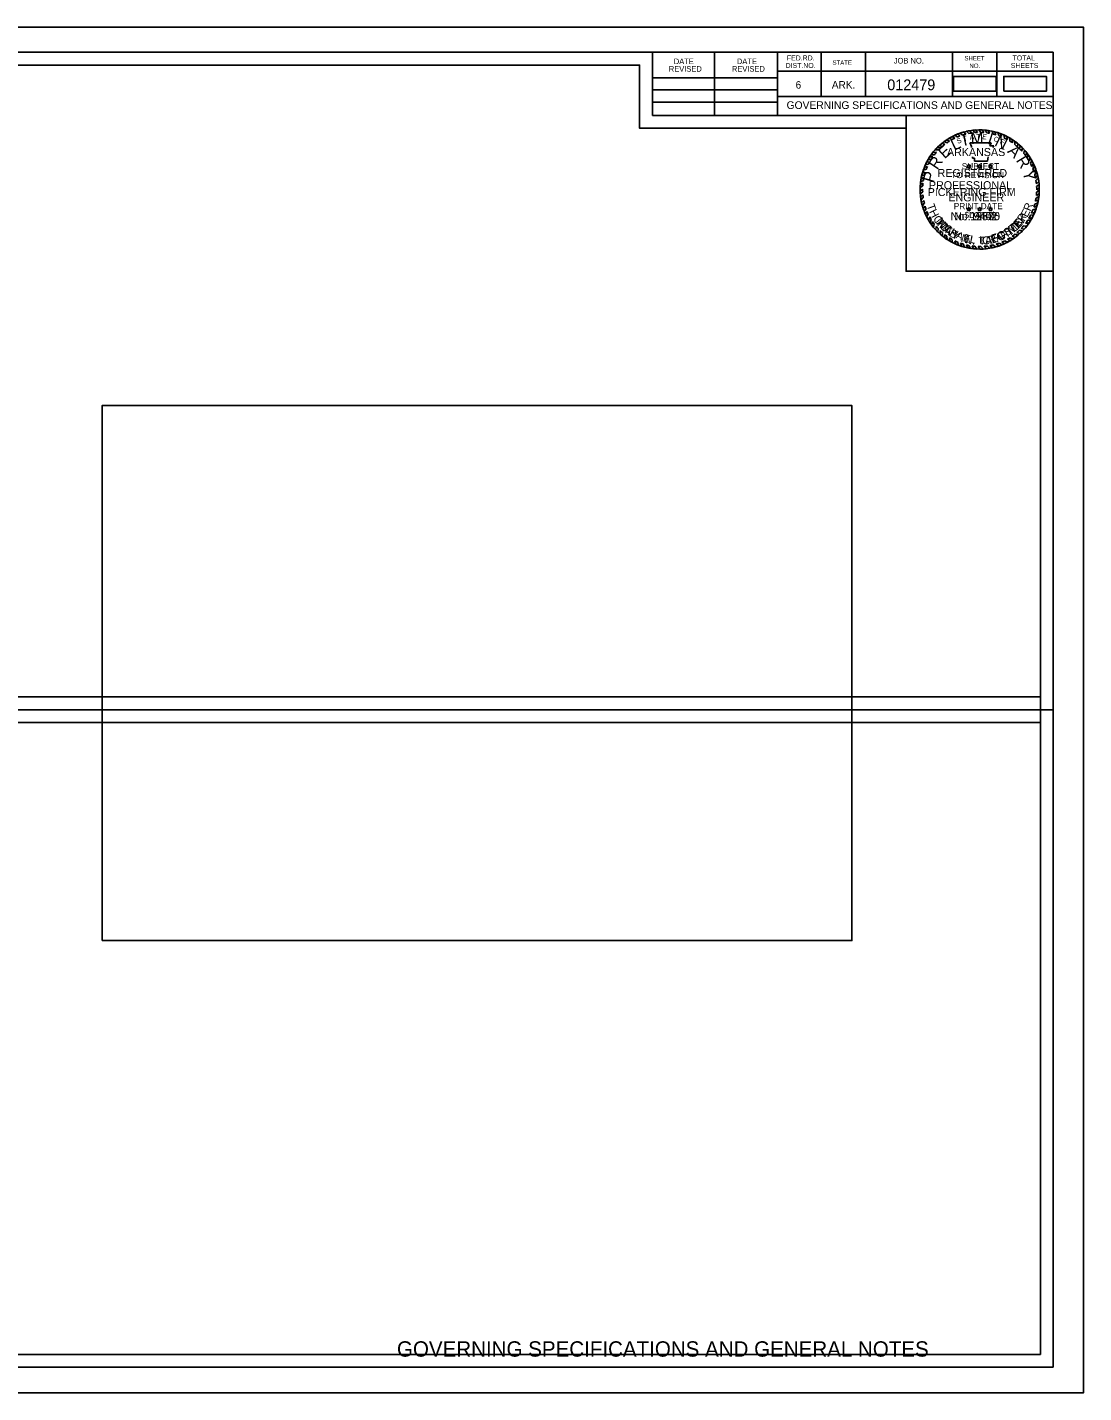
# Model space of a CAD drawing. Extents: x 1369290 to 1369980, y 379348 to 379562.
# Drawn here: x 1369815.1 to 1369980.2, y 379348.4 to 379561.7 of the extents above; entities that cross this region are included whole.
import ezdxf

# ---------------------------------------------------------------- set-up
doc = ezdxf.new("R2010")
doc.units = 0
for name, color, linetype in [('Default', 7, 'Continuous'), ('R_Border', 7, 'Continuous'), ('R_Border Notes', 7, 'Continuous'), ('R_Border Plan-Plan', 7, 'Continuous'), ('R_Border Title', 7, 'Continuous'), ('R_No Plot', 7, 'Continuous'), ('STAMP_PE_CRAFTON', 7, 'Continuous'), ('STAMP_PE_FOSTER', 7, 'Continuous'), ('STAMP_PE_SEAL-INFO', 7, 'Continuous'), ('STAMP_PE_TAEGTMEYER', 7, 'Continuous'), ('STAMP_PE_TXT', 7, 'Continuous'), ('STAMP_PRELIMINARY', 7, 'Continuous')]:
    doc.layers.add(name, color=color, linetype=linetype)

msp = doc.modelspace()

# ---------------------------------------------------------------- linework, layer by layer
at = {"layer": 'Default'}
for points in [[(1369959.8, 379551.74), (1369966.48, 379551.74), (1369966.48, 379554.05), (1369959.8, 379554.05)], [(1369967.67, 379551.74), (1369974.35, 379551.74), (1369974.35, 379554.05), (1369967.67, 379554.05)], [(1369826.78, 379419.02), (1369943.94, 379419.02), (1369943.94, 379502.63), (1369826.78, 379502.63)]]:
    msp.add_lwpolyline(points, close=True, dxfattribs=at)
at = {"layer": 'R_Border'}
for p, q in [((1369659.23, 379557.83), (1369975.41, 379557.83)), ((1369912.77, 379547.95), (1369912.77, 379557.83)), ((1369922.45, 379547.95), (1369922.45, 379557.83)), ((1369932.31, 379557.83), (1369932.31, 379547.95)), ((1369939.15, 379557.83), (1369939.15, 379550.89)), ((1369946.09, 379557.83), (1369946.09, 379550.89)), ((1369959.67, 379557.83), (1369959.67, 379550.89)), ((1369966.61, 379557.83), (1369966.61, 379550.89)), ((1369975.41, 379352.37), (1369975.41, 379557.83)), ((1369912.77, 379553.81), (1369932.31, 379553.81)), ((1369975.41, 379554.89), (1369932.31, 379554.89)), ((1369975.41, 379554.91), (1369975.41, 379554.91)), ((1369912.77, 379551.95), (1369932.31, 379551.95)), ((1369912.77, 379550.01), (1369932.31, 379550.01)), ((1369975.41, 379550.89), (1369932.31, 379550.89)), ((1369935.27, 379550.89), (1369975.41, 379550.89)), ((1369975.41, 379547.95), (1369912.77, 379547.95)), ((1369975.41, 379352.37), (1369659.23, 379352.37))]:
    msp.add_line(p, q, dxfattribs=at)
at = {"layer": 'R_Border Plan-Plan'}
msp.add_line((1369659.23, 379455.1), (1369975.41, 379455.1), dxfattribs=at)
at = {"layer": 'R_No Plot'}
for points in [[(1369646.82, 379561.73), (1369980.16, 379561.73), (1369980.16, 379348.39), (1369646.82, 379348.39)], [(1369973.41, 379457.1), (1369661.23, 379457.1), (1369661.23, 379555.83), (1369910.77, 379555.83), (1369910.77, 379545.95), (1369928.31, 379545.95), (1369952.41, 379545.95), (1369952.41, 379523.62), (1369973.41, 379523.62)], [(1369661.23, 379555.83), (1369910.77, 379555.83), (1369910.77, 379545.95), (1369928.31, 379545.95), (1369952.41, 379545.95), (1369952.41, 379523.62), (1369973.41, 379523.62), (1369973.41, 379354.37), (1369661.23, 379354.37)], [(1369952.41, 379547.95), (1369975.41, 379547.95), (1369975.41, 379523.62), (1369952.41, 379523.62)], [(1369661.23, 379453.1), (1369973.41, 379453.1), (1369973.41, 379354.37), (1369661.23, 379354.37)]]:
    msp.add_lwpolyline(points, close=True, dxfattribs=at)
at = {"layer": 'STAMP_PE_SEAL-INFO'}
for p, q in [((1369960.02, 379544.86), (1369960.41, 379544.59)), ((1369960.52, 379545.08), (1369960.82, 379544.75)), ((1369960.87, 379545.21), (1369961.25, 379544.9)), ((1369961.46, 379545.39), (1369961.75, 379545.04)), ((1369961.85, 379545.49), (1369962.21, 379545.14)), ((1369962.33, 379545.58), (1369962.63, 379545.22)), ((1369962.85, 379545.66), (1369963.13, 379545.27)), ((1369963.58, 379545.3), (1369963.27, 379545.7)), ((1369964.08, 379545.31), (1369963.8, 379545.72)), ((1369964.54, 379545.29), (1369964.28, 379545.71)), ((1369965.05, 379545.24), (1369964.75, 379545.68)), ((1369965.47, 379545.17), (1369965.21, 379545.63)), ((1369966.03, 379545.05), (1369965.86, 379545.51)), ((1369966.44, 379544.94), (1369966.28, 379545.41)), ((1369966.89, 379544.8), (1369966.75, 379545.28)), ((1369967.31, 379544.64), (1369967.16, 379545.13)), ((1369967.77, 379544.43), (1369967.66, 379544.93)), ((1369968.21, 379544.2), (1369968.13, 379544.71)), ((1369956.95, 379542.6), (1369957.47, 379542.56)), ((1369957.27, 379542.94), (1369957.82, 379542.9)), ((1369957.61, 379543.26), (1369958.07, 379543.12)), ((1369957.95, 379543.56), (1369958.48, 379543.46)), ((1369958.33, 379543.89), (1369958.79, 379543.69)), ((1369958.75, 379544.16), (1369959.19, 379543.96)), ((1369959.14, 379544.4), (1369959.57, 379544.18)), ((1369959.59, 379544.65), (1369960.05, 379544.43)), ((1369962.39, 379543.69), (1369965.73, 379543.69)), ((1369962.51, 379543.38), (1369962.39, 379543.69)), ((1369962.61, 379543.08), (1369962.51, 379543.38)), ((1369962.62, 379542.97), (1369962.61, 379543.08)), ((1369965.73, 379543.69), (1369965.5, 379543.19)), ((1369965.5, 379543.19), (1369966.14, 379543.19)), ((1369966.14, 379543.19), (1369965.99, 379542.97)), ((1369968.6, 379543.98), (1369968.56, 379544.48)), ((1369969.03, 379543.69), (1369969, 379544.2)), ((1369969.4, 379543.42), (1369969.43, 379543.91)), ((1369969.84, 379543.05), (1369969.86, 379543.57)), ((1369970.15, 379542.76), (1369970.22, 379543.26)), ((1369970.51, 379542.38), (1369970.58, 379542.91)), ((1369970.79, 379542.07), (1369970.92, 379542.54)), ((1369955.62, 379540.65), (1369956.11, 379540.71)), ((1369955.85, 379541.07), (1369956.34, 379541.09)), ((1369956.09, 379541.47), (1369956.61, 379541.5)), ((1369956.33, 379541.82), (1369956.83, 379541.81)), ((1369956.61, 379542.18), (1369957.15, 379542.21)), ((1369962.81, 379541.26), (1369962.78, 379541.48)), ((1369963.12, 379541.26), (1369962.81, 379541.26)), ((1369963.12, 379540.83), (1369963.12, 379541.26)), ((1369965.15, 379540.83), (1369963.12, 379540.83)), ((1369965.17, 379541.17), (1369965.15, 379540.83)), ((1369965.25, 379541.48), (1369965.17, 379541.17)), ((1369971.11, 379541.65), (1369971.25, 379542.15)), ((1369971.33, 379541.34), (1369971.51, 379541.8)), ((1369971.64, 379540.84), (1369971.82, 379541.33)), ((1369971.84, 379540.47), (1369972.07, 379540.92)), ((1369972.07, 379539.99), (1369972.3, 379540.47)), ((1369955.2, 379538.26), (1369954.73, 379538.01)), ((1369954.83, 379538.51), (1369955.3, 379538.7)), ((1369954.94, 379538.92), (1369955.41, 379539.08)), ((1369955.09, 379539.42), (1369955.58, 379539.56)), ((1369955.24, 379539.83), (1369955.75, 379539.97)), ((1369955.43, 379540.26), (1369955.93, 379540.36)), ((1369972.21, 379539.65), (1369972.47, 379540.08)), ((1369972.4, 379539.1), (1369972.68, 379539.58)), ((1369972.51, 379538.74), (1369972.81, 379539.19)), ((1369972.65, 379538.18), (1369972.96, 379538.63)), ((1369955.02, 379536.94), (1369954.59, 379536.69)), ((1369955, 379536.45), (1369954.59, 379536.11)), ((1369955.05, 379537.37), (1369954.62, 379537.09)), ((1369955.11, 379537.8), (1369954.67, 379537.58)), ((1369972.71, 379537.8), (1369973.07, 379538.15)), ((1369972.78, 379537.29), (1369973.15, 379537.63)), ((1369972.81, 379536.87), (1369973.2, 379537.16)), ((1369972.81, 379535.95), (1369973.23, 379536.22)), ((1369972.83, 379536.35), (1369973.23, 379536.67)), ((1369955.01, 379536.04), (1369954.61, 379535.72)), ((1369955.04, 379535.55), (1369954.67, 379535.19)), ((1369955.09, 379535.12), (1369954.74, 379534.74)), ((1369955.17, 379534.66), (1369954.83, 379534.29)), ((1369955.26, 379534.24), (1369954.95, 379533.83)), ((1369972.53, 379534.1), (1369973, 379534.3)), ((1369972.63, 379534.55), (1369973.09, 379534.75)), ((1369972.72, 379535.05), (1369973.17, 379535.27)), ((1369972.77, 379535.44), (1369973.21, 379535.7)), ((1369955.39, 379533.79), (1369955.09, 379533.38)), ((1369955.53, 379533.37), (1369955.25, 379532.96)), ((1369955.69, 379532.94), (1369955.43, 379532.52)), ((1369955.87, 379532.56), (1369955.64, 379532.1)), ((1369956.1, 379532.1), (1369955.91, 379531.61)), ((1369971.6, 379531.88), (1369972.1, 379531.93)), ((1369971.87, 379532.38), (1369972.36, 379532.44)), ((1369972.03, 379532.71), (1369972.52, 379532.81)), ((1369972.24, 379533.23), (1369972.73, 379533.36)), ((1369972.38, 379533.61), (1369972.87, 379533.81)), ((1369956.34, 379531.7), (1369956.15, 379531.23)), ((1369956.54, 379531.39), (1369956.43, 379530.83)), ((1369956.82, 379531), (1369956.72, 379530.47)), ((1369957.12, 379530.62), (1369957.04, 379530.1)), ((1369957.43, 379530.28), (1369957.36, 379529.76)), ((1369957.75, 379529.96), (1369957.72, 379529.43)), ((1369970.14, 379530.02), (1369970.58, 379529.88)), ((1369970.39, 379530.28), (1369970.87, 379530.19)), ((1369970.78, 379530.71), (1369971.24, 379530.63)), ((1369971.09, 379531.1), (1369971.59, 379531.11)), ((1369971.43, 379531.6), (1369971.9, 379531.59)), ((1369958.09, 379529.64), (1369958.09, 379529.11)), ((1369958.45, 379529.35), (1369958.47, 379528.82)), ((1369958.79, 379529.1), (1369958.83, 379528.58)), ((1369959.22, 379528.82), (1369959.28, 379528.3)), ((1369959.57, 379528.61), (1369959.66, 379528.1)), ((1369960.05, 379528.36), (1369960.21, 379527.84)), ((1369960.42, 379528.19), (1369960.6, 379527.68)), ((1369960.91, 379528), (1369961.12, 379527.5)), ((1369961.32, 379527.87), (1369961.55, 379527.38)), ((1369961.83, 379527.73), (1369962.04, 379527.26)), ((1369962.23, 379527.64), (1369962.48, 379527.18)), ((1369965.51, 379527.63), (1369965.9, 379527.29)), ((1369966.01, 379527.73), (1369966.38, 379527.41)), ((1369966.47, 379527.85), (1369966.88, 379527.56)), ((1369966.96, 379528.02), (1369967.4, 379527.75)), ((1369967.38, 379528.18), (1369967.8, 379527.92)), ((1369967.84, 379528.39), (1369968.32, 379528.18)), ((1369968.24, 379528.6), (1369968.66, 379528.37)), ((1369968.66, 379528.85), (1369969.11, 379528.65)), ((1369969, 379529.08), (1369969.44, 379528.89)), ((1369969.46, 379529.42), (1369969.93, 379529.27)), ((1369969.73, 379529.64), (1369970.21, 379529.52)), ((1369962.73, 379527.56), (1369962.97, 379527.12)), ((1369963.17, 379527.51), (1369963.44, 379527.08)), ((1369963.65, 379527.48), (1369963.95, 379527.07)), ((1369964.11, 379527.48), (1369964.45, 379527.09)), ((1369964.63, 379527.51), (1369964.96, 379527.13)), ((1369965.07, 379527.56), (1369965.44, 379527.2))]:
    msp.add_line(p, q, dxfattribs=at)
for radius, start, end in [(9.32, 111.3124, 114.7026), (8.91, 110.3086, 113.1659), (9.32, 105.2339, 109.0352), (8.91, 104.0352, 107.3615), (9.32, 99.7525, 102.7765), (8.91, 98.258, 101.0329), (9.32, 93.9381, 96.5517), (8.91, 92.1102, 95.0367), (9.32, 87.7298, 90.6707), (8.91, 85.9628, 88.9097), (9.32, 81.9732, 84.8236), (8.91, 79.9264, 82.696), (9.32, 75.3125, 77.9426), (8.91, 73.5575, 76.2314), (9.32, 69.6061, 72.3058), (8.91, 67.6248, 70.504), (9.32, 63.1329, 66.2704), (9.32, 135.4021, 138.3031), (8.91, 133.1331, 136.2562), (9.32, 129.7326, 132.5376), (8.91, 127.5297, 130.9683), (9.32, 123.6199, 126.5906), (8.91, 121.9746, 125.11), (9.32, 117.6544, 120.8099), (8.91, 115.6869, 119.1583), (8.91, 61.1558, 64.3784), (9.32, 56.9003, 60.0942), (8.91, 54.9238, 58.2702), (8.91, 48.3016, 52.0395), (9.32, 50.3492, 53.7159), (8.91, 42.2212, 45.5512), (9.32, 44.3405, 47.3929), (9.32, 38.1247, 41.2316), (9.32, 152.864, 155.5189), (9.32, 147.0072, 149.899), (8.91, 151.0315, 153.573), (9.32, 141.6056, 144.4486), (8.91, 145.0197, 148.2104), (8.91, 139.301, 142.5873), (8.91, 36.135, 39.5311), (8.91, 29.9032, 33.6645), (9.32, 31.9614, 35.4294), (8.91, 23.7732, 27.2211), (9.32, 25.9391, 29.0125), (9.32, 164.3068, 166.894), (9.32, 158.4077, 161.0701), (8.91, 167.9048, 170.9039), (8.91, 162.4331, 165.0013), (8.91, 156.3402, 159.2319), (8.91, 17.6802, 21.4251), (9.32, 19.9538, 23.3141), (8.91, 11.5444, 15.2364), (9.32, 13.8421, 17.4447), (9.32, 175.7409, 178.2066), (9.32, 170.0003, 172.6878), (8.91, 179.6454, 182.2633), (8.91, 173.73, 176.4734), (8.91, 5.7599, 9.0606), (8.91, 359.7329, 3.0639), (9.32, 7.5852, 10.8621), (9.32, 1.7215, 4.7268), (9.32, 355.7156, 358.9569), (9.32, 181.7251, 184.1626), (9.32, 187.4204, 190.1927), (9.32, 193.0369, 195.9973), (8.91, 185.4539, 188.234), (8.91, 191.2274, 193.9858), (8.91, 341.777, 345.0925), (8.91, 348.0778, 351.3435), (8.91, 353.8632, 357.1274), (9.32, 343.8925, 347.035), (9.32, 349.8305, 353.0885), (9.32, 198.8967, 201.6281), (8.91, 196.9675, 199.8353), (9.32, 204.5479, 207.4328), (8.91, 202.7761, 205.4791), (8.91, 208.7883, 211.7934), (8.91, 329.5549, 333.2076), (8.91, 335.6038, 339.1858), (9.32, 331.4037, 334.9332), (9.32, 337.3837, 340.9933), (9.32, 210.8636, 213.6571), (9.32, 216.6115, 219.491), (8.91, 214.1838, 217.2747), (9.32, 222.48, 225.3801), (8.91, 220.3909, 223.3056), (8.91, 226.2494, 229.2407), (8.91, 310.7744, 314.3161), (9.32, 312.4518, 315.6633), (8.91, 316.6531, 320.3711), (9.32, 318.2846, 321.8043), (8.91, 323.5851, 327.4407), (9.32, 325.4405, 328.9872), (9.32, 228.3665, 231.348), (8.91, 232.229, 234.9336), (9.32, 234.295, 236.9452), (8.91, 238.2223, 240.8353), (9.32, 240.1977, 242.8613), (8.91, 244.3204, 246.9486), (9.32, 246.576, 249.1558), (8.91, 250.3491, 253.1216), (8.91, 256.505, 259.1192), (8.91, 280.3459, 283.5814), (8.91, 286.6423, 289.9783), (9.32, 288.5709, 291.9733), (8.91, 292.8745, 296.1185), (9.32, 294.6481, 298.2166), (8.91, 299.0768, 302.1724), (9.32, 300.621, 303.8703), (8.91, 304.823, 308.5143), (9.32, 306.3721, 310.208), (9.32, 252.5967, 255.3252), (9.32, 258.4433, 261.1398), (8.91, 262.3783, 265.2012), (9.32, 264.1978, 267.1009), (8.91, 268.3215, 271.277), (9.32, 270.2548, 273.3361), (8.91, 274.6157, 277.4486), (9.32, 276.4239, 279.4357), (9.32, 282.3199, 285.3702)]:
    msp.add_arc((1369963.91, 379536.39), radius, start, end, dxfattribs=at)
at = {"layer": 'STAMP_PE_TXT'}
for p, q in [((1369962.09, 379539.97), (1369961.89, 379540.11)), ((1369961.89, 379540.11), (1369962.14, 379540.11)), ((1369962.02, 379539.73), (1369962.09, 379539.97)), ((1369962.21, 379539.88), (1369962.02, 379539.73)), ((1369962.14, 379540.11), (1369962.21, 379540.34)), ((1369962.21, 379540.34), (1369962.29, 379540.11)), ((1369962.41, 379539.73), (1369962.21, 379539.88)), ((1369962.29, 379540.11), (1369962.54, 379540.11)), ((1369962.54, 379540.11), (1369962.34, 379539.97)), ((1369962.34, 379539.97), (1369962.41, 379539.73)), ((1369963.79, 379539.97), (1369963.59, 379540.11)), ((1369963.59, 379540.11), (1369963.84, 379540.11)), ((1369963.71, 379539.73), (1369963.79, 379539.97)), ((1369963.91, 379539.88), (1369963.71, 379539.73)), ((1369963.84, 379540.11), (1369963.91, 379540.34)), ((1369963.91, 379540.34), (1369963.99, 379540.11)), ((1369964.11, 379539.73), (1369963.91, 379539.88)), ((1369963.99, 379540.11), (1369964.23, 379540.11)), ((1369964.23, 379540.11), (1369964.04, 379539.97)), ((1369964.04, 379539.97), (1369964.11, 379539.73)), ((1369965.49, 379539.97), (1369965.29, 379540.11)), ((1369965.29, 379540.11), (1369965.53, 379540.11)), ((1369965.41, 379539.73), (1369965.49, 379539.97)), ((1369965.61, 379539.88), (1369965.41, 379539.73)), ((1369965.53, 379540.11), (1369965.61, 379540.34)), ((1369965.61, 379540.34), (1369965.69, 379540.11)), ((1369965.81, 379539.73), (1369965.61, 379539.88)), ((1369965.69, 379540.11), (1369965.93, 379540.11)), ((1369965.93, 379540.11), (1369965.73, 379539.97)), ((1369965.73, 379539.97), (1369965.81, 379539.73)), ((1369962.09, 379533.26), (1369961.89, 379533.4)), ((1369961.89, 379533.4), (1369962.14, 379533.4)), ((1369962.02, 379533.03), (1369962.09, 379533.26)), ((1369962.21, 379533.17), (1369962.02, 379533.03)), ((1369962.14, 379533.4), (1369962.21, 379533.64)), ((1369962.21, 379533.64), (1369962.29, 379533.4)), ((1369962.41, 379533.03), (1369962.21, 379533.17)), ((1369962.29, 379533.4), (1369962.54, 379533.4)), ((1369962.54, 379533.4), (1369962.34, 379533.26)), ((1369962.34, 379533.26), (1369962.41, 379533.03)), ((1369963.79, 379533.26), (1369963.59, 379533.4)), ((1369963.59, 379533.4), (1369963.84, 379533.4)), ((1369963.71, 379533.03), (1369963.79, 379533.26)), ((1369963.91, 379533.17), (1369963.71, 379533.03)), ((1369963.84, 379533.4), (1369963.91, 379533.64)), ((1369963.91, 379533.64), (1369963.99, 379533.4)), ((1369964.11, 379533.03), (1369963.91, 379533.17)), ((1369963.99, 379533.4), (1369964.23, 379533.4)), ((1369964.23, 379533.4), (1369964.04, 379533.26)), ((1369964.04, 379533.26), (1369964.11, 379533.03)), ((1369965.49, 379533.26), (1369965.29, 379533.4)), ((1369965.29, 379533.4), (1369965.53, 379533.4)), ((1369965.41, 379533.03), (1369965.49, 379533.26)), ((1369965.61, 379533.17), (1369965.41, 379533.03)), ((1369965.53, 379533.4), (1369965.61, 379533.64)), ((1369965.61, 379533.64), (1369965.69, 379533.4)), ((1369965.81, 379533.03), (1369965.61, 379533.17)), ((1369965.69, 379533.4), (1369965.93, 379533.4)), ((1369965.93, 379533.4), (1369965.73, 379533.26)), ((1369965.73, 379533.26), (1369965.81, 379533.03))]:
    msp.add_line(p, q, dxfattribs=at)
at = {"layer": 'STAMP_PRELIMINARY'}
msp.add_circle((1369963.91, 379536.39), 9.32, dxfattribs=at)

# ---------------------------------------------------------------- texts
at = {"layer": 'R_Border'}
for s, height, p in [('REVISED', 0.879, (1369915.33, 379554.79)), ('DATE', 0.879, (1369916.11, 379555.97)), ('REVISED', 0.879, (1369925.19, 379554.79)), ('DATE', 0.879, (1369925.97, 379555.97)), ('DIST.NO.', 0.782, (1369933.59, 379555.37)), ('FED.RD.', 0.782, (1369933.79, 379556.55)), ('STATE', 0.684, (1369940.91, 379555.87)), ('JOB NO.', 0.879, (1369950.49, 379556.07)), ('SHEET', 0.684, (1369961.53, 379556.55)), ('NO.', 0.684, (1369962.31, 379555.37)), ('SHEETS', 0.782, (1369968.77, 379555.37)), ('TOTAL', 0.782, (1369969.05, 379556.55)), ('6', 1.17, (1369935.15, 379552.15)), ('ARK.', 1.172, (1369940.81, 379552.15))]:
    msp.add_text(s, height=height, dxfattribs=at).set_placement(p)
at = {"layer": 'R_Border Notes'}
for s, height, p in [('012479', 1.68, (1369949.47, 379551.9)), ('GOVERNING SPECIFICATIONS AND GENERAL NOTES', 1.2, (1369933.74, 379548.97))]:
    msp.add_text(s, height=height, dxfattribs=at).set_placement(p)
at = {"layer": 'R_Border Title'}
msp.add_text('GOVERNING SPECIFICATIONS AND GENERAL NOTES', height=2.4, dxfattribs=at).set_placement((1369872.85, 379354.02))
at = {"layer": 'STAMP_PE_CRAFTON'}
for s, rotation, p in [('T', 310.7442, (1369956.88, 379531.29)), ('N', 49.2411, (1369970.19, 379530.42)), ('O', 317.6422, (1369957.55, 379530.48)), ('N', 324.4537, (1369958.39, 379529.7)), ('Y', 331.1686, (1369959.42, 379528.98)), ('F', 28.7821, (1369967.57, 379528.52)), ('T', 34.1136, (1369968.49, 379529.03)), ('O', 41.8391, (1369969.35, 379529.64)), ('N', 347.4752, (1369961.48, 379528.06)), ('.', 356.8926, (1369962.71, 379527.79)), ('C', 6.0117, (1369964.38, 379527.74)), ('R', 14.8189, (1369965.48, 379527.85)), ('A', 20.5125, (1369966.59, 379528.15))]:
    msp.add_text(s, height=1.25, rotation=rotation, dxfattribs=at).set_placement(p)
msp.add_text('No. 12370', height=1.25, dxfattribs=at).set_placement((1369959.37, 379531.59))
at = {"layer": 'STAMP_PE_FOSTER'}
for s, rotation, p in [('M', 308.339, (1369957.03, 379531.42)), ('E', 46.9613, (1369969.91, 379530.38)), ('R', 54.5031, (1369970.64, 379531.21)), ('I', 314.1842, (1369957.83, 379530.48)), ('C', 319.8733, (1369958.18, 379530.13)), ('H', 327.7235, (1369959.11, 379529.39)), ('O', 23.719, (1369966.99, 379528.48)), ('S', 31.7234, (1369968.1, 379529.01)), ('T', 39.4194, (1369969.05, 379529.63)), ('A', 335.7276, (1369960.09, 379528.81)), ('E', 343.5779, (1369961.23, 379528.34)), ('L', 350.8115, (1369962.29, 379528.06)), ('L', 1.2666, (1369963.83, 379527.9)), ('.', 6.8035, (1369964.87, 379527.96)), ('F', 15.8691, (1369965.95, 379528.15))]:
    msp.add_text(s, height=1.2, rotation=rotation, dxfattribs=at).set_placement(p)
msp.add_text('No. 9402', height=1.25, dxfattribs=at).set_placement((1369959.9, 379531.59))
at = {"layer": 'STAMP_PE_TAEGTMEYER'}
for s, rotation, p in [('T', 289.646, (1369955.61, 379533.9)), ('R', 69.57, (1369971.86, 379532.91)), ('H', 296.7339, (1369955.97, 379532.92)), ('O', 303.7708, (1369956.56, 379531.81)), ('Y', 53.9986, (1369970.69, 379530.99)), ('E', 63.0984, (1369971.36, 379531.93)), ('M', 314.2033, (1369957.21, 379530.86)), ('A', 321.0594, (1369958.18, 379529.9)), ('S', 327.8239, (1369959, 379529.25)), ('G', 23.3052, (1369966.91, 379528.26)), ('T', 31.466, (1369968.01, 379528.75)), ('M', 39.3, (1369968.91, 379529.29)), ('E', 46.8094, (1369969.95, 379530.17)), ('N', 344.2727, (1369960.9, 379528.25)), ('.', 350.6464, (1369962.11, 379527.91)), ('T', 3.0061, (1369963.78, 379527.72)), ('A', 8.9826, (1369964.82, 379527.77)), ('E', 17.6836, (1369965.86, 379527.93))]:
    msp.add_text(s, height=1.25, rotation=rotation, dxfattribs=at).set_placement(p)
msp.add_text('No. 19605', height=1.25, dxfattribs=at).set_placement((1369959.37, 379531.59))
at = {"layer": 'STAMP_PE_TXT'}
for s, rotation, p in [('T', 16.311, (1369961.43, 379543.87)), ('A', 9.0679, (1369962.4, 379544.12)), ('T', 1.8248, (1369963.38, 379544.25)), ('E', 355.2002, (1369964.29, 379544.26)), ('O', 342.2506, (1369966.02, 379543.98)), ('S', 23.5541, (1369960.51, 379543.5)), ('F', 335.0075, (1369966.99, 379543.65))]:
    msp.add_text(s, height=0.781, rotation=rotation, dxfattribs=at).set_placement(p)
for s, p in [('ARKANSAS', (1369958.8, 379541.61)), ('REGISTERED', (1369957.33, 379538.34)), ('PROFESSIONAL', (1369955.98, 379536.43)), ('ENGINEER', (1369959.02, 379534.53))]:
    msp.add_text(s, height=1.25, dxfattribs=at).set_placement(p)
at = {"layer": 'STAMP_PRELIMINARY'}
for s, rotation, p in [('I', 12.5248, (1369961.45, 379543.18)), ('M', 3.1074, (1369962.55, 379543.49)), ('I', 342.3164, (1369965.02, 379543.56)), ('N', 333.9382, (1369966.12, 379543.28)), ('E', 42.3578, (1369958.44, 379541.09)), ('L', 25.513, (1369959.92, 379542.42)), ('A', 315.6579, (1369968.16, 379542.26)), ('R', 56.2292, (1369957.28, 379539.36)), ('R', 301.3831, (1369969.53, 379540.94)), ('P', 73.913, (1369956.73, 379537.34)), ('Y', 283.2593, (1369970.61, 379539.16))]:
    msp.add_text(s, height=1.8, rotation=rotation, dxfattribs=at).set_placement(p)
for s, height, p in [('SUBJECT', 0.96, (1369961.11, 379539.54)), ('TO REVISION', 0.96, (1369959.45, 379538.16)), ('PICKERING FIRM', 1.25, (1369955.79, 379535.36)), ('PRINT DATE', 0.96, (1369959.87, 379533.31)), ('$DATE$', 0.96, (1369961.55, 379531.93))]:
    msp.add_text(s, height=height, dxfattribs=at).set_placement(p)

doc.saveas('drawing.dxf')
